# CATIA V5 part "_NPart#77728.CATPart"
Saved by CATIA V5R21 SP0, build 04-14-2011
Part number: Imãs
Definition: Imãs
Nomenclature: Imãs
Source: Unknown
Bounding box of the stored display mesh (mm): x -5.773 to 5.773, y 0 to 8.5, z -4.808 to 4.808
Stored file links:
  C:\Users\beatr\OneDrive\Documents\UNB\2026_1\Pi1\Componentes eletronicos\_NPart#77728.CATPart
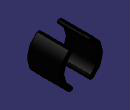
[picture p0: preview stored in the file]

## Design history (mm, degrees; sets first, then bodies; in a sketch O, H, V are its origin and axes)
Body1 "Sólido1" (main body)
  Solid1: solid without history
Body2 "Sólido1"
  Solid2: solid without history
